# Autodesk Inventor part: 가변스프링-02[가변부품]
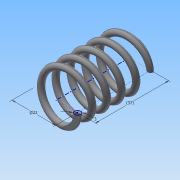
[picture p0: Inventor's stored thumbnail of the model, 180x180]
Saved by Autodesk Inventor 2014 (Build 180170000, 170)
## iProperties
Created: 2015-09
Part Number: 가변스프링-02[가변부품]
Material: 강철, 탄소
Document SubType Name: Modeling
Designer: study
Density: 7.87 g/cm^3
Appearance: 반연마
Mass: 18.7976 g
Surface Area: 32.4648 cm^2
Volume: 2.38851 cm^3
Author: study
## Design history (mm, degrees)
sketch "스케치1"
  geometry: L1 (0, 0)-(11, 0); L2 (11, 0)-(11, 36.411); L3 (11, 36.411)-(0, 36.411); L4 (0, 36.411)-(0, 0); C1 r 1.5 at (11, 0)
  constraints: 8 end point, 2 parallel, 1 centre point, 1 coincident, 1 horizontal, 1 perpendicular
  dimensions: "d0" = 22 diameter of L2 L4; "d1" = 36.4112 distance of L1.end L2.end (derived); "d2" = 3 diameter of C1
feature "코일1" sketch "스케치1" pitch "d3" = 10; turns "d5" = 5; dims "d4" = 36.4112 (= d1), "d6" = 0, angle "d7" = 90 deg, angle "d8" = 90 deg, "d9" = 0, "d10" = 0
sketch "스케치2"
  geometry: L1 (-12.5, 0)-(-9.5, 0) reference; L2 (-12.5, 0)-(-9.5, 0) reference; 1 further point
  constraints: 2 horizontal alignment
extrude "돌출1" cut sketch "스케치2" stored distance "d11" = 10; taper "d12" = 0 deg
node "작업 평면1"
sketch "스케치3"
  geometry: L1 (-9.5, 0)-(-12.5, 0) reference; 1 further point
  constraints: 1 horizontal alignment
extrude "돌출2" cut sketch "스케치3" stored distance "d14" = 10; taper "d15" = 0 deg
node "솔리드1"
node "절단 모서리 투영1"
node "절단 모서리 투영2"
node "절단 모서리 투영3"
other parameters: "d13" = 36.4112 (= d1)
